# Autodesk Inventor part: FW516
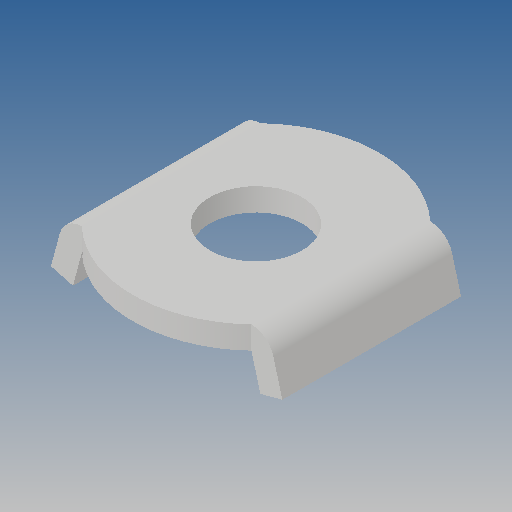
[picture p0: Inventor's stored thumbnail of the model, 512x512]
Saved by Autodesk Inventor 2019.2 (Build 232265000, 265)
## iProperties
Created: 2011-12
Part Number: FW516
Material: Ogólny
Document SubType Name: Modeling
Designer: CADENGINEERING4
Density: 1 g/cm^3
Appearance: Domyślna
Author: CADENGINEERING4
Revision Number: ÈÎºÎ
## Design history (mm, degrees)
feature "ÇÐ³ý-À­Éì4"
node "Bryła1"
